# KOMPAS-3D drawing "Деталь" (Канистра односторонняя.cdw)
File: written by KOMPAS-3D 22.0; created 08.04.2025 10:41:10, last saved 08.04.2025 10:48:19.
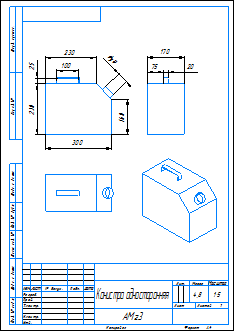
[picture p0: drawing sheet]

Sheet 1: A4, portrait

Document properties: Автор: Admin; Масса: 4.798699; Полное имя файла: Канистра односторонняя.m3d

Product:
- Part/product: Деталь
    Масса: 4.798699

Title block, sheet 1: Наименование: Канистра односторонняя; Материал: АМг3; Масса: 4,8; Количество листов документа: 1; Форматы листов документа: A4; stored path: D:\28.11.2016\Абилимпикс\2025\Канистра односторонняя.cdw

Views: Вид 1, Спереди, Проекционный вид 2, Проекционный вид 3, Проекционный вид 4
Referenced files in D:\28.11.2016\Абилимпикс\2025\: Канистра односторонняя.m3d
Dimensions and other numbers on the sheet: 230; 300; 160; 50; 100; 25; 75; 20; 170; 1:5; 1; 4,8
